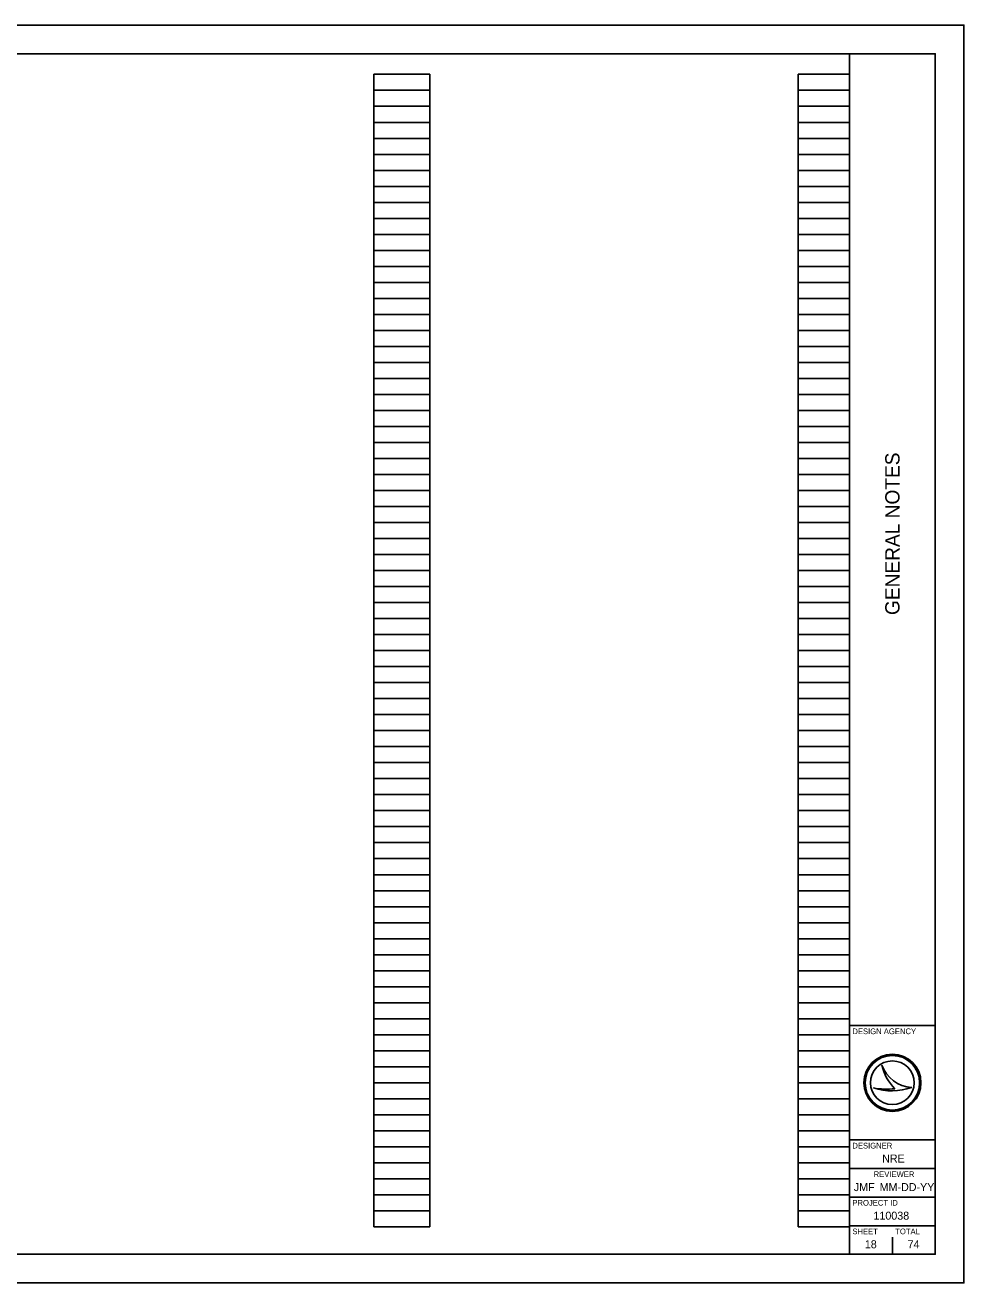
# Model space of a CAD drawing. Extents: x 0 to 34, y 0 to 22.
# Drawn here: x 17.58 to 34, y 0 to 22 of the extents above; entities that cross this region are included whole.
import ezdxf

# ---------------------------------------------------------------- set-up
doc = ezdxf.new("R2010")
doc.units = 0
for name, color, linetype in [('SH_Border', 7, 'Continuous'), ('SH_Cut_Line', 7, 'Continuous'), ('SH_Data', 7, 'Continuous')]:
    doc.layers.add(name, color=color, linetype=linetype)

msp = doc.modelspace()

# ---------------------------------------------------------------- linework, layer by layer
at = {"layer": 'SH_Border'}
for p, q in [((32, 0.5), (32, 21.5)), ((32, 4.5), (33.5, 4.5)), ((32, 2.5), (33.5, 2.5)), ((32, 2), (33.5, 2)), ((32, 1.5), (33.5, 1.5)), ((32, 1), (33.5, 1))]:
    msp.add_line(p, q, dxfattribs=at)
msp.add_lwpolyline([(1.5, 21.5), (33.5, 21.5), (33.5, 0.5), (1.5, 0.5)], close=True, dxfattribs=at)
at = {"layer": 'SH_Cut_Line'}
msp.add_lwpolyline([(0, 0), (34, 0), (34, 22), (0, 22)], close=True, dxfattribs=at)
at = {"layer": 'SH_Data'}
for p, q in [((23.68, 0.98), (23.68, 21.14)), ((23.68, 21.14), (24.66, 21.14)), ((24.66, 0.98), (24.66, 21.14)), ((31.1, 0.98), (31.1, 21.14)), ((31.1, 21.14), (32, 21.14)), ((32, 0.98), (32, 21.14)), ((23.68, 20.86), (24.66, 20.86)), ((31.1, 20.86), (32, 20.86)), ((23.68, 20.58), (24.66, 20.58)), ((31.1, 20.58), (32, 20.58)), ((23.68, 20.3), (24.66, 20.3)), ((31.1, 20.3), (32, 20.3)), ((23.68, 20.02), (24.66, 20.02)), ((31.1, 20.02), (32, 20.02)), ((23.68, 19.74), (24.66, 19.74)), ((31.1, 19.74), (32, 19.74)), ((23.68, 19.46), (24.66, 19.46)), ((31.1, 19.46), (32, 19.46)), ((23.68, 19.18), (24.66, 19.18)), ((31.1, 19.18), (32, 19.18)), ((23.68, 18.9), (24.66, 18.9)), ((31.1, 18.9), (32, 18.9)), ((23.68, 18.62), (24.66, 18.62)), ((31.1, 18.62), (32, 18.62)), ((23.68, 18.34), (24.66, 18.34)), ((31.1, 18.34), (32, 18.34)), ((23.68, 18.06), (24.66, 18.06)), ((31.1, 18.06), (32, 18.06)), ((23.68, 17.78), (24.66, 17.78)), ((31.1, 17.78), (32, 17.78)), ((23.68, 17.5), (24.66, 17.5)), ((31.1, 17.5), (32, 17.5)), ((23.68, 17.22), (24.66, 17.22)), ((31.1, 17.22), (32, 17.22)), ((23.68, 16.94), (24.66, 16.94)), ((31.1, 16.94), (32, 16.94)), ((23.68, 16.66), (24.66, 16.66)), ((31.1, 16.66), (32, 16.66)), ((23.68, 16.38), (24.66, 16.38)), ((31.1, 16.38), (32, 16.38)), ((23.68, 16.1), (24.66, 16.1)), ((31.1, 16.1), (32, 16.1)), ((23.68, 15.82), (24.66, 15.82)), ((31.1, 15.82), (32, 15.82)), ((23.68, 15.54), (24.66, 15.54)), ((31.1, 15.54), (32, 15.54)), ((23.68, 15.26), (24.66, 15.26)), ((31.1, 15.26), (32, 15.26)), ((23.68, 14.98), (24.66, 14.98)), ((31.1, 14.98), (32, 14.98)), ((23.68, 14.7), (24.66, 14.7)), ((31.1, 14.7), (32, 14.7)), ((23.68, 14.42), (24.66, 14.42)), ((31.1, 14.42), (32, 14.42)), ((23.68, 14.14), (24.66, 14.14)), ((31.1, 14.14), (32, 14.14)), ((23.68, 13.86), (24.66, 13.86)), ((31.1, 13.86), (32, 13.86)), ((23.68, 13.58), (24.66, 13.58)), ((31.1, 13.58), (32, 13.58)), ((23.68, 13.3), (24.66, 13.3)), ((31.1, 13.3), (32, 13.3)), ((23.68, 13.02), (24.66, 13.02)), ((31.1, 13.02), (32, 13.02)), ((23.68, 12.74), (24.66, 12.74)), ((31.1, 12.74), (32, 12.74)), ((23.68, 12.46), (24.66, 12.46)), ((31.1, 12.46), (32, 12.46)), ((23.68, 12.18), (24.66, 12.18)), ((31.1, 12.18), (32, 12.18)), ((23.68, 11.9), (24.66, 11.9)), ((31.1, 11.9), (32, 11.9)), ((23.68, 11.62), (24.66, 11.62)), ((31.1, 11.62), (32, 11.62)), ((23.68, 11.34), (24.66, 11.34)), ((31.1, 11.34), (32, 11.34)), ((23.68, 11.06), (24.66, 11.06)), ((31.1, 11.06), (32, 11.06)), ((23.68, 10.78), (24.66, 10.78)), ((31.1, 10.78), (32, 10.78)), ((23.68, 10.5), (24.66, 10.5)), ((31.1, 10.5), (32, 10.5)), ((23.68, 10.22), (24.66, 10.22)), ((31.1, 10.22), (32, 10.22)), ((23.68, 9.94), (24.66, 9.94)), ((31.1, 9.94), (32, 9.94)), ((23.68, 9.66), (24.66, 9.66)), ((31.1, 9.66), (32, 9.66)), ((23.68, 9.38), (24.66, 9.38)), ((31.1, 9.38), (32, 9.38)), ((23.68, 9.1), (24.66, 9.1)), ((31.1, 9.1), (32, 9.1)), ((23.68, 8.82), (24.66, 8.82)), ((31.1, 8.82), (32, 8.82)), ((23.68, 8.54), (24.66, 8.54)), ((31.1, 8.54), (32, 8.54)), ((23.68, 8.26), (24.66, 8.26)), ((31.1, 8.26), (32, 8.26)), ((23.68, 7.98), (24.66, 7.98)), ((31.1, 7.98), (32, 7.98)), ((23.68, 7.7), (24.66, 7.7)), ((31.1, 7.7), (32, 7.7)), ((23.68, 7.42), (24.66, 7.42)), ((31.1, 7.42), (32, 7.42)), ((23.68, 7.14), (24.66, 7.14)), ((31.1, 7.14), (32, 7.14)), ((23.68, 6.86), (24.66, 6.86)), ((31.1, 6.86), (32, 6.86)), ((23.68, 6.58), (24.66, 6.58)), ((31.1, 6.58), (32, 6.58)), ((23.68, 6.3), (24.66, 6.3)), ((31.1, 6.3), (32, 6.3)), ((23.68, 6.02), (24.66, 6.02)), ((31.1, 6.02), (32, 6.02)), ((23.68, 5.74), (24.66, 5.74)), ((31.1, 5.74), (32, 5.74)), ((23.68, 5.46), (24.66, 5.46)), ((31.1, 5.46), (32, 5.46)), ((23.68, 5.18), (24.66, 5.18)), ((31.1, 5.18), (32, 5.18)), ((23.68, 4.9), (24.66, 4.9)), ((31.1, 4.9), (32, 4.9)), ((23.68, 4.62), (24.66, 4.62)), ((31.1, 4.62), (32, 4.62)), ((23.68, 4.34), (24.66, 4.34)), ((31.1, 4.34), (32, 4.34)), ((23.68, 4.06), (24.66, 4.06)), ((31.1, 4.06), (32, 4.06)), ((23.68, 3.78), (24.66, 3.78)), ((31.1, 3.78), (32, 3.78)), ((32.567, 3.81), (32.567, 3.81)), ((23.68, 3.5), (24.66, 3.5)), ((31.1, 3.5), (32, 3.5)), ((32.417, 3.41), (32.417, 3.41)), ((32.75, 3.5), (32.75, 3.5)), ((33.087, 3.419), (33.087, 3.419)), ((23.68, 3.22), (24.66, 3.22)), ((31.1, 3.22), (32, 3.22)), ((23.68, 2.94), (24.66, 2.94)), ((31.1, 2.94), (32, 2.94)), ((23.68, 2.66), (24.66, 2.66)), ((31.1, 2.66), (32, 2.66)), ((23.68, 2.38), (24.66, 2.38)), ((31.1, 2.38), (32, 2.38)), ((23.68, 2.1), (24.66, 2.1)), ((31.1, 2.1), (32, 2.1)), ((23.68, 1.82), (24.66, 1.82)), ((31.1, 1.82), (32, 1.82)), ((23.68, 1.54), (24.66, 1.54)), ((31.1, 1.54), (32, 1.54)), ((23.68, 1.26), (24.66, 1.26)), ((31.1, 1.26), (32, 1.26)), ((23.68, 0.98), (24.66, 0.98)), ((31.1, 0.98), (32, 0.98)), ((32.375, 0.675), (32.375, 0.675)), ((32.75, 0.5), (32.75, 0.8))]:
    msp.add_line(p, q, dxfattribs=at)
for radius in [0.5, 0.477, 0.477, 0.382]:
    msp.add_circle((32.75, 3.5), radius, dxfattribs=at)
for centre, radius, start, end in [((33.116, 3.998), 0.58, 198.9257, 198.9319), ((33.347, 3.97), 0.796, 191.6379, 191.6421), ((33.116, 3.998), 0.58, 198.9319, 267.1657), ((33.347, 3.97), 0.796, 191.6421, 226.0947), ((32.739, 4.37), 1.013, 251.4576, 290.0832), ((32.648, 4.654), 1.266, 259.4964, 259.4995), ((32.739, 4.37), 1.013, 251.4527, 251.4576), ((32.648, 4.654), 1.266, 259.4995, 276.6672)]:
    msp.add_arc(centre, radius, start, end, dxfattribs=at)

# ---------------------------------------------------------------- texts
msp.add_text('GENERAL NOTES', height=0.25, rotation=90, dxfattribs=at).set_placement((32.875, 11.682))
for s, height, p in [('DESIGN AGENCY', 0.1, (32.05, 4.35)), ('DESIGNER', 0.1, (32.05, 2.35)), ('NRE', 0.14, (32.571, 2.105)), ('REVIEWER', 0.1, (32.422, 1.85)), ('JMF', 0.14, (32.075, 1.605)), ('MM-DD-YY', 0.14, (32.527, 1.605)), ('PROJECT ID', 0.1, (32.05, 1.35)), ('110038', 0.14, (32.419, 1.105)), ('SHEET', 0.1, (32.05, 0.85)), ('TOTAL', 0.1, (32.8, 0.85)), ('18', 0.14, (32.268, 0.605)), ('74', 0.14, (33.016, 0.605))]:
    msp.add_text(s, height=height, dxfattribs=at).set_placement(p)

doc.saveas('drawing.dxf')
